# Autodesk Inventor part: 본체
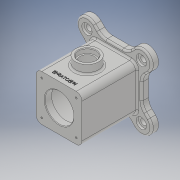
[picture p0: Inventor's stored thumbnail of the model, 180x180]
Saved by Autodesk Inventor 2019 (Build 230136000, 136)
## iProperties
Created: 2021-01
Part Number: 본체
Material: 일반
Document SubType Name: Modeling
Designer: 3dpro14
Density: 1 g/cm^3
Appearance: 기본값
Mass: 385.913 g
Surface Area: 854.915 cm^2
Volume: 385.913 cm^3
Author: 3dpro14
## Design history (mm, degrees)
sketch "스케치1" dims "d26" = 134
  geometry: L1 (22.544, -48)-(-22.544, -48); L2 (-48, -22.544)-(-48, 22.544); L3 (-22.544, 48)-(22.544, 48); L4 (48, 22.544)-(48, -22.544); L5 (60.104, -34.648)-(48, -22.544); L6 (34.648, -60.104)-(22.544, -48); L7 (-34.648, -60.104)-(-22.544, -48); L8 (-60.104, -34.648)-(-48, -22.544); L9 (-60.104, 34.648)-(-48, 22.544); L10 (-34.648, 60.104)-(-22.544, 48); L11 (34.648, 60.104)-(22.544, 48); L12 (60.104, 34.648)-(48, 22.544); L13 (-115.707, 0)-(118.741, 0); L14 (97.225, -97.225)-(-79.645, 79.645); L15 (0, -95.249)-(0, 88.026); L16 (95.516, 0)-(-98.205, 0); L17 (-70.337, -70.337)-(68.388, 68.388); A1 r 18 centre (47.376, -47.376) between (33.054, -58.279) and (58.279, -33.054); A2 r 18 centre (-47.376, -47.376) between (-58.279, -33.054) and (-33.054, -58.279); A3 r 18 centre (-47.376, 47.376) between (-33.054, 58.279) and (-58.279, 33.054); A4 r 18 centre (47.376, 47.376) between (58.279, 33.054) and (33.054, 58.279); 2 further points
  constraints: 34 end point, 16 point on circle, 8 tangent, 7 equal length, 7 point on line, 6 parallel, 4 centre point, 4 perpendicular, 2 horizontal, 1 coincident, 1 vertical, 14 other
  dimensions: "d0" = 96 distance between parallel lines of L3 L1; "d1" = 96 distance between parallel lines of L4 L2; "d2" = 48 distance from line of point (0, 0) L4 (= 0.5 x d1); "d3" = 48 distance from line of point (0, 0) L1 (= 0.5 x d0); "d27" = 36 distance between parallel lines of L6 L5; "d28" = 45 deg angle of L14 L16; "d29" = 45 deg angle of L17 L15; "d30" = 45 deg angle of L13 L14
extrude "돌출1" new body sketch "스케치1" distance "d5" = 12; taper "d6" = 0 deg
fillet "모깎기1" dims "d7" = 20
sketch "스케치2"
  geometry: L1 (40, -40)-(-40, -40); L2 (-40, -40)-(-40, 40); L3 (-40, 40)-(40, 40); L4 (40, 40)-(40, -40); L5 (40, -40)-(-40, 40); L6 (-40, -40)-(40, 40); 1 further point
  constraints: 12 end point, 2 midpoint, 2 parallel, 1 horizontal, 1 perpendicular
  dimensions: "d8" = 80 distance of L1.end L2.end; "d9" = 80 distance of L1.start L1.end
extrude "돌출2" join sketch "스케치2" distance "d10" = 96; taper "d11" = 0 deg
sketch "스케치3"
  geometry: C1 r 25 at (0, 0); 1 further point
  constraints: 1 centre point, 1 coincident
  dimensions: "d12" = 50 diameter of C1
extrude "돌출3" cut sketch "스케치3" distance "d13" = 12; taper "d14" = 0 deg
sketch "스케치4"
  geometry: C1 r 35 at (0, 0); 1 further point
  constraints: 1 centre point, 1 coincident
  dimensions: "d15" = 70 diameter of C1
extrude "돌출4" cut sketch "스케치4" distance "d16" = 84; taper "d17" = 0 deg
sketch "스케치5"
  geometry: C1 r 25 at (0, 0) reference; 1 further point
extrude "돌출5" cut sketch "스케치5" extent not by distance; stored distance "d18" = 84; taper "d19" = 0 deg
fillet "모깎기2" dims "d20" = 3
chamfer "모따기1" distance "d21" = 1; stored, may be unused: second distance "d22" = 2, angle "d23" = 45 deg
sketch "스케치6"
  geometry: L1 (54.26, 0)-(25.74, 0) reference; L2 (54.26, -12)-(25.74, -12) reference; C1 r 20 at (40, 47); 2 further points
  constraints: 1 centre point, 1 midpoint, 1 vertical alignment
  dimensions: "d24" = 59 distance from line of C1.centre L2; "d25" = 40 diameter of C1
extrude "돌출6" join sketch "스케치6" distance "d31" = 15; taper "d32" = 0 deg
sketch "스케치7"
  geometry: C1 r 20 at (0, 0) reference; 2 further points
  constraints: 1 coincident
hole "구멍1" sketch "스케치7" at (0, 0) diameter "d33" = 25; stored, may be unused: countersink angle "d37" = 90 deg, drill point angle "d39" = 0 deg; dims "d34" = 6, "d35" = 30, "d36" = 8, "d38" = 8
sketch "스케치8"
  geometry: L1 (54.26, 0)-(25.74, 0) reference; L2 (0, 96)-(80, 96) reference; 3 further points
  constraints: 1 midpoint, 1 vertical alignment, 1 other
  dimensions: "d40" = 10 distance from line of point (40, 86) L2
feature "엠보싱1" sketch "스케치8" dims "d3" = 48 (= 0.5 x d0), "d41" = 0.5, "d42" = 0
sketch "스케치9"
  geometry: L1 (-40, 40)-(-40, -40) reference; L2 (40, 40)-(-40, 40) reference; 2 further points
  dimensions: "d43" = 10 distance from line of L1 point (-30, 30); "d44" = 10 distance from line of L2 point (-30, 30)
hole "구멍2" sketch "스케치9" at (-30, 30) diameter "d45" = 3.242; stored, may be unused: countersink angle "d49" = 90 deg, drill point angle "d51" = 118 deg; dims "d46" = 8, "d47" = 4, "d48" = 2, "d50" = 10
sketch "스케치10" dims "d58" = 134
  geometry: L1 (0, 107.205)-(0, -112.361); L2 (-96.353, 96.353)-(89.916, -89.916); 3 further points
  constraints: 4 end point, 3 point on line, 1 coincident, 1 vertical, 3 other
  dimensions: "d59" = 45 deg angle of L2 L1
hole "구멍3" sketch "스케치10" at (-47.376, 47.376) diameter "d60" = 10; stored, may be unused: countersink angle "d64" = 90 deg, drill point angle "d66" = 118 deg; dims "d61" = 8, "d62" = 18, "d63" = 4, "d65" = 10
fillet "모깎기3" dims "d70" = 10
sketch "스케치11"
  geometry: C1 r 1.621 at (30, 30) reference; 2 further points
  constraints: 1 coincident
hole "구멍4" sketch "스케치11" at (30, 30) diameter "d71" = 3.242; stored, may be unused: countersink angle "d75" = 90 deg, drill point angle "d77" = 118 deg; dims "d72" = 8, "d73" = 4, "d74" = 2, "d76" = 10
fillet "모깎기4" dims "d84" = 3
fillet "모깎기5" dims "d85" = 3
chamfer "모따기2" distance "d86" = 1; stored, may be unused: second distance "d87" = 2, angle "d88" = 45 deg
node "솔리드1"
pattern_linear "직사각형 패턴1" dims "d54" = 60, "d57" = 60
pattern_circular "원형 패턴1" dims angle "d68" = 360 deg
pattern_linear "직사각형 패턴2" dims "d80" = 60, "d83" = 60
